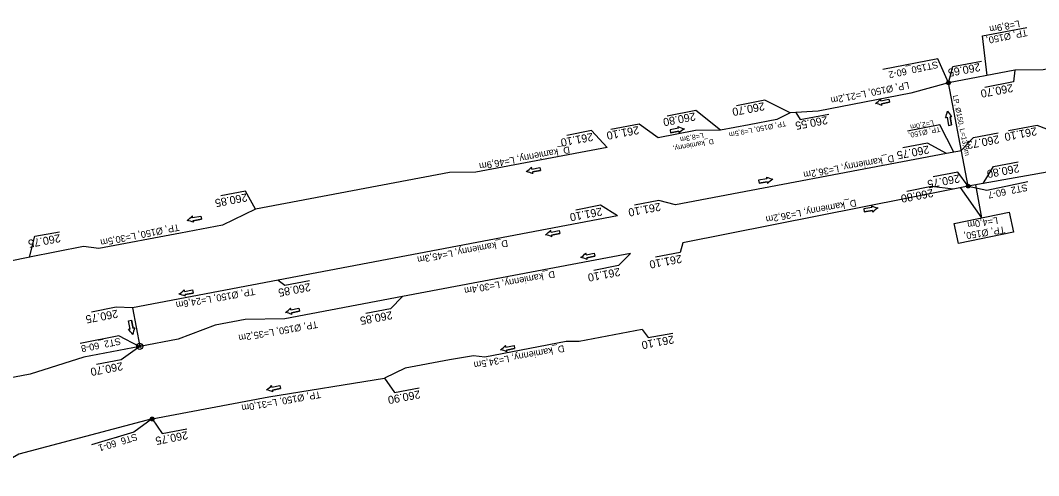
# Model space of a CAD drawing. Extents: x -1 to 65640748, y -22 to 5530284.
# Drawn here: x 6558492.6 to 6558626.1, y 5528855 to 5528914.8 of the extents above; entities that cross this region are included whole.
import ezdxf

# ---------------------------------------------------------------- set-up
doc = ezdxf.new("R2010")
doc.units = 0
for name, color, linetype in [('TOR_PROF-studnie i osadniki', 7, 'Continuous'), ('TOR_PS_ODW-drenaze', 7, 'Continuous'), ('TOR_PS_ODW-drenokolektory', 7, 'Continuous'), ('TOR_PS_ODW-studnie PEHD', 7, 'Continuous'), ('TOR_PS_OPIS_O-opisy rurociagow', 7, 'Continuous'), ('TOR_PS_OPIS_O-opisy studni', 7, 'Continuous'), ('TOR_PS_OPIS_T-INFO', 7, 'Continuous')]:
    doc.layers.add(name, color=color, linetype=linetype)

msp = doc.modelspace()

# ---------------------------------------------------------------- linework, layer by layer
at = {"layer": 'TOR_PROF-studnie i osadniki'}
for centre, radius in [((6558614.3, 5528906.61), 0.25), ((6558614.3, 5528906.61), 0.125), ((6558616.87, 5528893.04), 0.25), ((6558616.87, 5528893.04), 0.125)]:
    msp.add_circle(centre, radius, dxfattribs=at)
at = {"layer": 'TOR_PS_ODW-drenaze'}
msp.add_line((6558570.9, 5528889.13), (6558526.37, 5528880.68), dxfattribs=at)
for points in [[(6558656.59, 5528914.22), (6558634.14, 5528909.97), (6558632.79, 5528909.46), (6558626.73, 5528908.31), (6558622.98, 5528908.26)], [(6558622.98, 5528908.26), (6558614.3, 5528906.61)], [(6558614.3, 5528906.61), (6558609.34, 5528905.24), (6558597.2, 5528902.88), (6558593.51, 5528902.67)], [(6558593.51, 5528902.67), (6558593.51, 5528902.67), (6558591.8, 5528901.77), (6558588.13, 5528901.07), (6558588.13, 5528901.07), (6558584.38, 5528900.36)], [(6558675.13, 5528903.74), (6558642.81, 5528897.62), (6558618.84, 5528893.39)], [(6558584.38, 5528900.36), (6558581.09, 5528900.32), (6558576.21, 5528899.39)], [(6558569.51, 5528898.12), (6558552.29, 5528894.86), (6558548.84, 5528894.82), (6558523.38, 5528889.99)], [(6558614.03, 5528897.3), (6558578.5, 5528890.57)], [(6558615.99, 5528897.67), (6558614.03, 5528897.3)], [(6558615.99, 5528897.67), (6558614.03, 5528897.3)], [(6558618.84, 5528893.39), (6558616.87, 5528893.04)], [(6558614.91, 5528892.65), (6558579.44, 5528885.6)], [(6558616.87, 5528893.04), (6558614.91, 5528892.65)], [(6558523.38, 5528889.99), (6558519.07, 5528887.91), (6558513.56, 5528886.87), (6558502.83, 5528884.84), (6558500.85, 5528885.11), (6558493.75, 5528883.71)], [(6558572.57, 5528884.2), (6558542.67, 5528878.53)], [(6558493.82, 5528883.72), (6558464.9, 5528877.85)], [(6558526.37, 5528880.68), (6558507.26, 5528877.06), (6558508.22, 5528872)], [(6558542.67, 5528878.53), (6558527.23, 5528875.61), (6558522.05, 5528875.54), (6558518.12, 5528874.79), (6558513.27, 5528872.96), (6558508.22, 5528872.01)], [(6558574.1, 5528874.21), (6558565.87, 5528872.65), (6558564.14, 5528872.63), (6558553.46, 5528870.6), (6558552, 5528870.75), (6558548.85, 5528870.23), (6558543.03, 5528869.14), (6558540.34, 5528867.84)], [(6558509.85, 5528862.48), (6558525.14, 5528865.39), (6558540.34, 5528867.84)]]:
    msp.add_lwpolyline(points, dxfattribs=at)
at = {"layer": 'TOR_PS_ODW-drenokolektory'}
msp.add_line((6558616.87, 5528893.04), (6558614.3, 5528906.61), dxfattribs=at)
for points in [[(6558614.3, 5528906.61), (6558614.3, 5528906.61), (6558609.34, 5528905.24), (6558597.2, 5528902.88), (6558593.51, 5528902.67)], [(6558508.22, 5528872), (6558500.87, 5528870.61), (6558493.85, 5528868.34), (6558475.97, 5528864.95), (6558470.65, 5528864.64), (6558458.14, 5528862.24)], [(6558509.85, 5528862.48), (6558492.36, 5528857.86), (6558489.83, 5528856.4), (6558484.81, 5528855.05), (6558481.79, 5528855.04)]]:
    msp.add_lwpolyline(points, dxfattribs=at)
at = {"layer": 'TOR_PS_ODW-studnie PEHD'}
for centre, radius in [((6558614.3, 5528906.61), 0.25), ((6558614.3, 5528906.61), 0.112), ((6558616.87, 5528893.04), 0.25), ((6558616.87, 5528893.04), 0.112), ((6558508.22, 5528872), 0.4), ((6558508.22, 5528872), 0.145), ((6558509.85, 5528862.48), 0.25), ((6558509.85, 5528862.48), 0.112)]:
    msp.add_circle(centre, radius, dxfattribs=at)
at = {"layer": 'TOR_PS_OPIS_O-opisy rurociagow'}
for p, q in [((6558605.42, 5528904.23), (6558606.49, 5528904.45)), ((6558605.42, 5528904.23), (6558606.49, 5528904.45)), ((6558606.57, 5528904.06), (6558605.5, 5528903.84)), ((6558605.5, 5528903.84), (6558606.57, 5528904.06)), ((6558606.49, 5528904.45), (6558606.57, 5528904.06)), ((6558606.49, 5528904.45), (6558606.57, 5528904.06)), ((6558614.11, 5528902.08), (6558614.31, 5528901)), ((6558614.11, 5528902.08), (6558614.31, 5528901)), ((6558614.7, 5528901.08), (6558614.5, 5528902.15)), ((6558614.5, 5528902.15), (6558614.7, 5528901.08)), ((6558578.86, 5528900.62), (6558577.78, 5528900.43)), ((6558578.86, 5528900.62), (6558577.78, 5528900.43)), ((6558577.78, 5528900.43), (6558577.85, 5528900.04)), ((6558577.78, 5528900.43), (6558577.85, 5528900.04)), ((6558577.85, 5528900.04), (6558578.93, 5528900.23)), ((6558578.93, 5528900.23), (6558577.85, 5528900.04)), ((6558614.31, 5528901), (6558614.7, 5528901.08)), ((6558614.31, 5528901), (6558614.7, 5528901.08)), ((6558559.64, 5528895.28), (6558560.71, 5528895.5)), ((6558559.64, 5528895.28), (6558560.71, 5528895.5)), ((6558560.79, 5528895.1), (6558559.72, 5528894.89)), ((6558559.72, 5528894.89), (6558560.79, 5528895.1)), ((6558560.71, 5528895.5), (6558560.79, 5528895.1)), ((6558560.71, 5528895.5), (6558560.79, 5528895.1)), ((6558590.46, 5528894.01), (6558589.39, 5528893.82)), ((6558590.46, 5528894.01), (6558589.39, 5528893.82)), ((6558589.39, 5528893.82), (6558589.46, 5528893.42)), ((6558589.39, 5528893.82), (6558589.46, 5528893.42)), ((6558589.46, 5528893.42), (6558590.53, 5528893.62)), ((6558590.53, 5528893.62), (6558589.46, 5528893.42)), ((6558604.25, 5528890.23), (6558603.18, 5528890.04)), ((6558604.25, 5528890.23), (6558603.18, 5528890.04)), ((6558603.18, 5528890.04), (6558603.25, 5528889.65)), ((6558603.18, 5528890.04), (6558603.25, 5528889.65)), ((6558603.25, 5528889.65), (6558604.32, 5528889.84)), ((6558604.32, 5528889.84), (6558603.25, 5528889.65)), ((6558515.15, 5528888.9), (6558516.22, 5528889.11)), ((6558515.15, 5528888.9), (6558516.22, 5528889.11)), ((6558516.3, 5528888.72), (6558515.23, 5528888.5)), ((6558515.23, 5528888.5), (6558516.3, 5528888.72)), ((6558516.22, 5528889.11), (6558516.3, 5528888.72)), ((6558516.22, 5528889.11), (6558516.3, 5528888.72)), ((6558562.16, 5528887.01), (6558563.23, 5528887.23)), ((6558562.16, 5528887.01), (6558563.23, 5528887.23)), ((6558563.31, 5528886.83), (6558562.23, 5528886.62)), ((6558562.23, 5528886.62), (6558563.31, 5528886.83)), ((6558563.23, 5528887.23), (6558563.31, 5528886.83)), ((6558563.23, 5528887.23), (6558563.31, 5528886.83)), ((6558566.77, 5528884.02), (6558567.84, 5528884.24)), ((6558566.77, 5528884.02), (6558567.84, 5528884.24)), ((6558567.92, 5528883.85), (6558566.84, 5528883.63)), ((6558566.84, 5528883.63), (6558567.92, 5528883.85)), ((6558567.84, 5528884.24), (6558567.92, 5528883.85)), ((6558567.84, 5528884.24), (6558567.92, 5528883.85)), ((6558514.08, 5528879.19), (6558515.15, 5528879.41)), ((6558514.08, 5528879.19), (6558515.15, 5528879.41)), ((6558515.23, 5528879.01), (6558514.16, 5528878.8)), ((6558514.16, 5528878.8), (6558515.23, 5528879.01)), ((6558515.15, 5528879.41), (6558515.23, 5528879.01)), ((6558515.15, 5528879.41), (6558515.23, 5528879.01)), ((6558528.03, 5528876.81), (6558529.1, 5528877.02)), ((6558528.03, 5528876.81), (6558529.1, 5528877.02)), ((6558529.18, 5528876.63), (6558528.11, 5528876.41)), ((6558528.11, 5528876.41), (6558529.18, 5528876.63)), ((6558529.1, 5528877.02), (6558529.18, 5528876.63)), ((6558529.1, 5528877.02), (6558529.18, 5528876.63)), ((6558506.73, 5528875.35), (6558507.12, 5528875.43)), ((6558506.73, 5528875.35), (6558507.12, 5528875.43)), ((6558506.95, 5528874.28), (6558506.73, 5528875.35)), ((6558506.95, 5528874.28), (6558506.73, 5528875.35)), ((6558507.12, 5528875.43), (6558507.34, 5528874.36)), ((6558507.34, 5528874.36), (6558507.12, 5528875.43)), ((6558556.24, 5528871.91), (6558557.31, 5528872.13)), ((6558556.24, 5528871.91), (6558557.31, 5528872.13)), ((6558557.31, 5528872.13), (6558557.39, 5528871.73)), ((6558557.31, 5528872.13), (6558557.39, 5528871.73)), ((6558557.39, 5528871.73), (6558556.32, 5528871.52)), ((6558556.32, 5528871.52), (6558557.39, 5528871.73)), ((6558525.54, 5528866.65), (6558526.61, 5528866.86)), ((6558525.54, 5528866.65), (6558526.61, 5528866.86)), ((6558526.69, 5528866.47), (6558525.62, 5528866.25)), ((6558525.62, 5528866.25), (6558526.69, 5528866.47)), ((6558526.61, 5528866.86), (6558526.69, 5528866.47)), ((6558526.61, 5528866.86), (6558526.69, 5528866.47))]:
    msp.add_line(p, q, dxfattribs=at)
for points in [[(6558605.39, 5528904.45), (6558605.39, 5528904.45)], [(6558605.56, 5528903.62), (6558605.56, 5528903.62)], [(6558613.89, 5528902.03), (6558613.89, 5528902.03)], [(6558614.72, 5528902.18), (6558614.72, 5528902.18)], [(6558578.81, 5528900.84), (6558578.81, 5528900.84)], [(6558578.96, 5528900.01), (6558578.96, 5528900.01)], [(6558559.61, 5528895.5), (6558559.61, 5528895.5)], [(6558559.77, 5528894.67), (6558559.77, 5528894.67)], [(6558590.41, 5528894.23), (6558590.41, 5528894.23)], [(6558590.56, 5528893.39), (6558590.56, 5528893.39)], [(6558604.2, 5528890.45), (6558604.2, 5528890.45)], [(6558604.35, 5528889.61), (6558604.35, 5528889.61)], [(6558515.12, 5528889.12), (6558515.12, 5528889.12)], [(6558515.28, 5528888.29), (6558515.28, 5528888.29)], [(6558562.12, 5528887.23), (6558562.12, 5528887.23)], [(6558562.29, 5528886.4), (6558562.29, 5528886.4)], [(6558566.73, 5528884.25), (6558566.73, 5528884.25)], [(6558566.9, 5528883.41), (6558566.9, 5528883.41)], [(6558514.04, 5528879.41), (6558514.04, 5528879.41)], [(6558514.21, 5528878.58), (6558514.21, 5528878.58)], [(6558528, 5528877.03), (6558528, 5528877.03)], [(6558528.17, 5528876.2), (6558528.17, 5528876.2)], [(6558506.72, 5528874.24), (6558506.72, 5528874.24)], [(6558507.56, 5528874.41), (6558507.56, 5528874.41)], [(6558556.21, 5528872.13), (6558556.21, 5528872.13)], [(6558556.38, 5528871.3), (6558556.38, 5528871.3)], [(6558525.51, 5528866.87), (6558525.51, 5528866.87)], [(6558525.68, 5528866.04), (6558525.68, 5528866.04)]]:
    msp.add_lwpolyline(points, dxfattribs=at)
for centre, radius, start, end in [((6558601.91, 5528907.93), 4.92, 304.7037, 315.0855), ((6558601.91, 5528907.93), 4.92, 304.7037, 315.0855), ((6558603.69, 5528899.07), 4.92, 67.6658, 78.0476), ((6558603.69, 5528899.07), 4.92, 67.6658, 78.0476), ((6558604.97, 5528904.28), 0.458, 354.5097, 22.9709), ((6558604.97, 5528904.28), 0.458, 354.5097, 22.9709), ((6558605.1, 5528903.62), 0.458, 359.7803, 28.2416), ((6558605.1, 5528903.62), 0.458, 359.7803, 28.2416), ((6558609.36, 5528903.94), 4.92, 337.0234, 347.4052), ((6558609.36, 5528903.94), 4.92, 337.0234, 347.4052), ((6558618.23, 5528905.63), 4.92, 214.0613, 224.4431), ((6558618.23, 5528905.63), 4.92, 214.0613, 224.4431), ((6558613.89, 5528902.48), 0.458, 269.1379, 297.5992), ((6558613.89, 5528902.48), 0.458, 269.1379, 297.5992), ((6558614.55, 5528902.61), 0.458, 263.8673, 292.3285), ((6558614.55, 5528902.61), 0.458, 263.8673, 292.3285), ((6558580.78, 5528905.35), 4.92, 246.381, 256.7628), ((6558579.26, 5528900.83), 0.458, 178.4955, 206.9568), ((6558580.78, 5528905.35), 4.92, 246.381, 256.7628), ((6558579.26, 5528900.83), 0.458, 178.4955, 206.9568), ((6558579.38, 5528900.18), 0.458, 173.2249, 201.6861), ((6558579.38, 5528900.18), 0.458, 173.2249, 201.6861), ((6558582.36, 5528896.46), 4.92, 123.4189, 133.8007), ((6558582.36, 5528896.46), 4.92, 123.4189, 133.8007), ((6558556.12, 5528898.98), 4.92, 304.7037, 315.0855), ((6558556.12, 5528898.98), 4.92, 304.7037, 315.0855), ((6558557.91, 5528890.12), 4.92, 67.6658, 78.0476), ((6558557.91, 5528890.12), 4.92, 67.6658, 78.0476), ((6558559.19, 5528895.32), 0.458, 354.5097, 22.9709), ((6558559.19, 5528895.32), 0.458, 354.5097, 22.9709), ((6558559.32, 5528894.67), 0.458, 359.7803, 28.2416), ((6558559.32, 5528894.67), 0.458, 359.7803, 28.2416), ((6558592.38, 5528898.74), 4.92, 246.381, 256.7628), ((6558590.87, 5528894.22), 0.458, 178.4955, 206.9568), ((6558592.38, 5528898.74), 4.92, 246.381, 256.7628), ((6558590.87, 5528894.22), 0.458, 178.4955, 206.9568), ((6558590.99, 5528893.56), 0.458, 173.2249, 201.6861), ((6558590.99, 5528893.56), 0.458, 173.2249, 201.6861), ((6558593.97, 5528889.84), 4.92, 123.4189, 133.8007), ((6558593.97, 5528889.84), 4.92, 123.4189, 133.8007), ((6558606.17, 5528894.96), 4.92, 246.381, 256.7628), ((6558604.66, 5528890.44), 0.458, 178.4955, 206.9568), ((6558606.17, 5528894.96), 4.92, 246.381, 256.7628), ((6558604.66, 5528890.44), 0.458, 178.4955, 206.9568), ((6558604.78, 5528889.78), 0.458, 173.2249, 201.6861), ((6558604.78, 5528889.78), 0.458, 173.2249, 201.6861), ((6558607.76, 5528886.06), 4.92, 123.4189, 133.8007), ((6558607.76, 5528886.06), 4.92, 123.4189, 133.8007), ((6558511.63, 5528892.59), 4.92, 304.7037, 315.0855), ((6558511.63, 5528892.59), 4.92, 304.7037, 315.0855), ((6558513.42, 5528883.74), 4.92, 67.6658, 78.0476), ((6558513.42, 5528883.74), 4.92, 67.6658, 78.0476), ((6558514.7, 5528888.94), 0.458, 354.5097, 22.9709), ((6558514.7, 5528888.94), 0.458, 354.5097, 22.9709), ((6558514.83, 5528888.29), 0.458, 359.7803, 28.2416), ((6558514.83, 5528888.29), 0.458, 359.7803, 28.2416), ((6558558.64, 5528890.71), 4.92, 304.7037, 315.0855), ((6558558.64, 5528890.71), 4.92, 304.7037, 315.0855), ((6558560.42, 5528881.85), 4.92, 67.6658, 78.0476), ((6558560.42, 5528881.85), 4.92, 67.6658, 78.0476), ((6558561.7, 5528887.05), 0.458, 354.5097, 22.9709), ((6558561.7, 5528887.05), 0.458, 354.5097, 22.9709), ((6558561.83, 5528886.4), 0.458, 359.7803, 28.2416), ((6558561.83, 5528886.4), 0.458, 359.7803, 28.2416), ((6558563.25, 5528887.72), 4.92, 304.7037, 315.0855), ((6558563.25, 5528887.72), 4.92, 304.7037, 315.0855), ((6558566.31, 5528884.07), 0.458, 354.5097, 22.9709), ((6558566.31, 5528884.07), 0.458, 354.5097, 22.9709), ((6558565.03, 5528878.86), 4.92, 67.6658, 78.0476), ((6558565.03, 5528878.86), 4.92, 67.6658, 78.0476), ((6558566.44, 5528883.42), 0.458, 359.7803, 28.2416), ((6558566.44, 5528883.42), 0.458, 359.7803, 28.2416), ((6558510.56, 5528882.89), 4.92, 304.7037, 315.0855), ((6558510.56, 5528882.89), 4.92, 304.7037, 315.0855), ((6558512.34, 5528874.03), 4.92, 67.6658, 78.0476), ((6558512.34, 5528874.03), 4.92, 67.6658, 78.0476), ((6558513.62, 5528879.23), 0.458, 354.5097, 22.9709), ((6558513.62, 5528879.23), 0.458, 354.5097, 22.9709), ((6558513.75, 5528878.58), 0.458, 359.7803, 28.2416), ((6558513.75, 5528878.58), 0.458, 359.7803, 28.2416), ((6558524.52, 5528880.5), 4.92, 304.7037, 315.0855), ((6558524.52, 5528880.5), 4.92, 304.7037, 315.0855), ((6558526.3, 5528871.65), 4.92, 67.6658, 78.0476), ((6558526.3, 5528871.65), 4.92, 67.6658, 78.0476), ((6558527.58, 5528876.85), 0.458, 354.5097, 22.9709), ((6558527.58, 5528876.85), 0.458, 354.5097, 22.9709), ((6558527.71, 5528876.2), 0.458, 359.7803, 28.2416), ((6558527.71, 5528876.2), 0.458, 359.7803, 28.2416), ((6558506.9, 5528873.82), 0.458, 84.5097, 112.9709), ((6558506.9, 5528873.82), 0.458, 84.5097, 112.9709), ((6558503.25, 5528870.76), 4.92, 34.7037, 45.0855), ((6558503.25, 5528870.76), 4.92, 34.7037, 45.0855), ((6558512.11, 5528872.54), 4.92, 157.6658, 168.0476), ((6558512.11, 5528872.54), 4.92, 157.6658, 168.0476), ((6558507.55, 5528873.95), 0.458, 89.7803, 118.2416), ((6558507.55, 5528873.95), 0.458, 89.7803, 118.2416), ((6558552.73, 5528875.61), 4.92, 304.7037, 315.0855), ((6558552.73, 5528875.61), 4.92, 304.7037, 315.0855), ((6558555.79, 5528871.96), 0.458, 354.5097, 22.9709), ((6558555.79, 5528871.96), 0.458, 354.5097, 22.9709), ((6558554.51, 5528866.75), 4.92, 67.6658, 78.0476), ((6558554.51, 5528866.75), 4.92, 67.6658, 78.0476), ((6558555.92, 5528871.3), 0.458, 359.7803, 28.2416), ((6558555.92, 5528871.3), 0.458, 359.7803, 28.2416), ((6558522.03, 5528870.34), 4.92, 304.7037, 315.0855), ((6558522.03, 5528870.34), 4.92, 304.7037, 315.0855), ((6558525.09, 5528866.69), 0.458, 354.5097, 22.9709), ((6558525.09, 5528866.69), 0.458, 354.5097, 22.9709), ((6558523.81, 5528861.49), 4.92, 67.6658, 78.0476), ((6558523.81, 5528861.49), 4.92, 67.6658, 78.0476), ((6558525.22, 5528866.04), 0.458, 359.7803, 28.2416), ((6558525.22, 5528866.04), 0.458, 359.7803, 28.2416)]:
    msp.add_arc(centre, radius, start, end, dxfattribs=at)
at = {"layer": 'TOR_PS_OPIS_T-INFO'}
for q in [(6558617.86, 5528893.21), (6558615.89, 5528892.84)]:
    msp.add_line((6558618.65, 5528888.89), q, dxfattribs=at)
for points in [[(6558619.37, 5528907.56), (6558618.74, 5528912.77), (6558624.55, 5528913.86)], [(6558614.3, 5528906.61), (6558612.91, 5528909.72), (6558605.68, 5528908.33)], [(6558614.3, 5528906.61), (6558614.86, 5528908.74), (6558618.61, 5528909.44)], [(6558622.98, 5528908.26), (6558622.8, 5528906.7), (6558619.06, 5528905.98)], [(6558593.51, 5528902.67), (6558590.22, 5528904.3), (6558586.47, 5528903.58)], [(6558584.38, 5528900.36), (6558581.15, 5528902.96), (6558577.4, 5528902.23)], [(6558594.26, 5528902.71), (6558594.83, 5528901.79), (6558598.58, 5528902.49)], [(6558569.51, 5528898.12), (6558567.45, 5528900.32), (6558564.22, 5528899.7)], [(6558576.21, 5528899.39), (6558573.74, 5528901.17), (6558570, 5528900.45)], [(6558615.01, 5528897.49), (6558613.15, 5528901.08), (6558608.9, 5528900.26)], [(6558615.96, 5528897.69), (6558617.58, 5528899.42), (6558620.81, 5528900.03)], [(6558628.46, 5528900.04), (6558625.91, 5528901.01), (6558622.17, 5528900.29)], [(6558614.03, 5528897.3), (6558611.53, 5528898.66), (6558608.3, 5528898.04)], [(6558618.84, 5528893.39), (6558620.21, 5528895.61), (6558623.44, 5528896.21)], [(6558616.87, 5528893.04), (6558615.54, 5528894.86), (6558612.3, 5528894.24)], [(6558616.87, 5528893.04), (6558619.32, 5528892.5), (6558624.72, 5528893.63)], [(6558523.38, 5528889.99), (6558522.09, 5528892.39), (6558518.86, 5528891.76)], [(6558614.91, 5528892.65), (6558612.07, 5528892.97), (6558608.84, 5528892.34)], [(6558570.9, 5528889.13), (6558568.63, 5528890.53), (6558565.4, 5528889.9)], [(6558578.5, 5528890.57), (6558576.32, 5528891.15), (6558573.09, 5528890.53)], [(6558493.75, 5528883.71), (6558494.44, 5528886.45), (6558497.68, 5528887.05)], [(6558579.44, 5528885.6), (6558579.08, 5528884.32), (6558575.85, 5528883.7)], [(6558572.57, 5528884.2), (6558571, 5528882.6), (6558567.77, 5528881.98)], [(6558526.37, 5528880.68), (6558527.24, 5528880.03), (6558530.48, 5528880.63)], [(6558542.68, 5528878.54), (6558541.11, 5528876.94), (6558537.88, 5528876.31)], [(6558507.26, 5528877.06), (6558505.12, 5528877.13), (6558501.89, 5528876.51)], [(6558508.12, 5528871.97), (6558505.48, 5528873.37), (6558500.39, 5528872.39)], [(6558574.11, 5528874.21), (6558574.91, 5528873.15), (6558578.15, 5528873.75)], [(6558508.22, 5528872.01), (6558505.77, 5528870.24), (6558502.53, 5528869.61)], [(6558540.34, 5528867.84), (6558541.63, 5528865.95), (6558544.87, 5528866.55)], [(6558509.91, 5528862.53), (6558507.46, 5528860.76), (6558501.91, 5528859.08)], [(6558509.85, 5528862.48), (6558511.14, 5528860.59), (6558514.38, 5528861.19)]]:
    msp.add_lwpolyline(points, dxfattribs=at)
msp.add_lwpolyline([(6558622.8, 5528886.99), (6558615.59, 5528885.5), (6558615.04, 5528888.15), (6558622.25, 5528889.63)], close=True, dxfattribs=at)

# ---------------------------------------------------------------- texts
at = {"layer": 'TOR_PS_OPIS_O-opisy rurociagow'}
for s, height, rotation, p in [('L=8,9m', 0.9, 191.2986, (6558623.56, 5528914.81)), ('TP, Ø150, ', 0.9, 191.2986, (6558624.55, 5528913.63)), ('LP, Ø150, L=21,2m', 0.9, 191.2986, (6558609.04, 5528906.73)), ('LP, Ø150, L=13,8m', 0.675, 281.6253, (6558614.85, 5528904.91)), ('TP, Ø150, L=9,5m', 0.675, 191.2986, (6558592.93, 5528901.58)), (' L=2,0m', 0.675, 191.2986, (6558612.55, 5528901.75)), ('L=8,3m', 0.675, 190.5985, (6558582.12, 5528900.03)), ('TP, Ø150,', 0.675, 191.2986, (6558613.16, 5528900.84)), ('D_kamienny, ', 0.675, 190.5985, (6558583.44, 5528899.25)), ('D_kamienny, L=46,9m', 0.9, 190.5985, (6558564.54, 5528898.26)), ('D_kamienny, L=36,2m', 0.9, 190.5985, (6558607.07, 5528897.13)), ('D_kamienny, L=36,2m', 0.9, 190.5985, (6558602.13, 5528891.29)), ('TP, Ø150, L=30,5m', 0.9, 191.3285, (6558513.32, 5528888.09)), ('L=4,0m', 0.9, 189.0325, (6558620.71, 5528888.99)), ('TP, Ø150,', 0.9, 189.0325, (6558621.65, 5528887.77)), ('D_kamienny, L=45,3m', 0.9, 190.5985, (6558556.42, 5528886)), ('D_kamienny, L=30,4m', 0.9, 190.5985, (6558562.59, 5528881.92)), ('TP, Ø150, L=24,6m', 0.9, 189.9416, (6558523.27, 5528879.66)), ('TP, Ø150, L=35,2m', 0.9, 189.9416, (6558531.49, 5528875.33)), ('D_kamienny, L=34,5m', 0.9, 190.5985, (6558563.83, 5528872.18)), ('TP, Ø150, L=31,0m', 0.9, 189.9416, (6558531.89, 5528866.14))]:
    msp.add_text(s, height=height, rotation=rotation, dxfattribs=at).set_placement(p)
at = {"layer": 'TOR_PS_OPIS_O-opisy studni'}
for s, rotation, p in [('ST150_60-2', 192.2213, (6558612.83, 5528909.44)), ('ST2_60-7', 191.2536, (6558624.57, 5528893.31)), ('ST2_60-8', 191.3925, (6558505.63, 5528873.14)), ('ST6_60-1', 196.9499, (6558507.75, 5528860.59))]:
    msp.add_text(s, height=0.9, rotation=rotation, dxfattribs=at).set_placement(p)
at = {"layer": 'TOR_PS_OPIS_T-INFO'}
for s, rotation, p in [('260.65', 190.7506, (6558618.37, 5528909.19)), ('260.70', 190.7159, (6558622.66, 5528906.45)), ('260.70', 190.7159, (6558590.08, 5528904.05)), ('260.80', 190.7159, (6558581.01, 5528902.71)), ('260.55', 190.7506, (6558598.34, 5528902.24)), ('261.10', 190.7159, (6558567.58, 5528900.03)), ('261.10', 190.7159, (6558573.6, 5528900.93)), ('261.10', 190.7159, (6558625.78, 5528900.77)), ('260.73', 190.8016, (6558620.85, 5528899.72)), ('260.75', 190.7159, (6558611.66, 5528898.37)), ('260.80', 190.7506, (6558623.48, 5528895.91)), ('260.75', 190.7159, (6558615.67, 5528894.57)), ('260.85', 190.7159, (6558522.22, 5528892.09)), ('260.80', 190.7159, (6558612.2, 5528892.67)), ('261.10', 190.7159, (6558576.45, 5528890.86)), ('261.10', 190.7159, (6558568.77, 5528890.23)), ('260.75', 190.7506, (6558497.72, 5528886.75)), ('261.10', 190.7159, (6558579.21, 5528884.03)), ('261.10', 190.7159, (6558571.13, 5528882.31)), ('260.85', 190.7506, (6558530.52, 5528880.33)), ('260.75', 190.7159, (6558505.26, 5528876.83)), ('260.85', 190.7159, (6558541.25, 5528876.64)), ('261.10', 190.7506, (6558578.19, 5528873.45)), ('260.70', 190.7159, (6558505.9, 5528869.94)), ('260.90', 190.7506, (6558544.91, 5528866.25)), ('260.75', 190.7506, (6558514.42, 5528860.89))]:
    msp.add_text(s, height=1.05, rotation=rotation, dxfattribs=at).set_placement(p)

doc.saveas('drawing.dxf')
